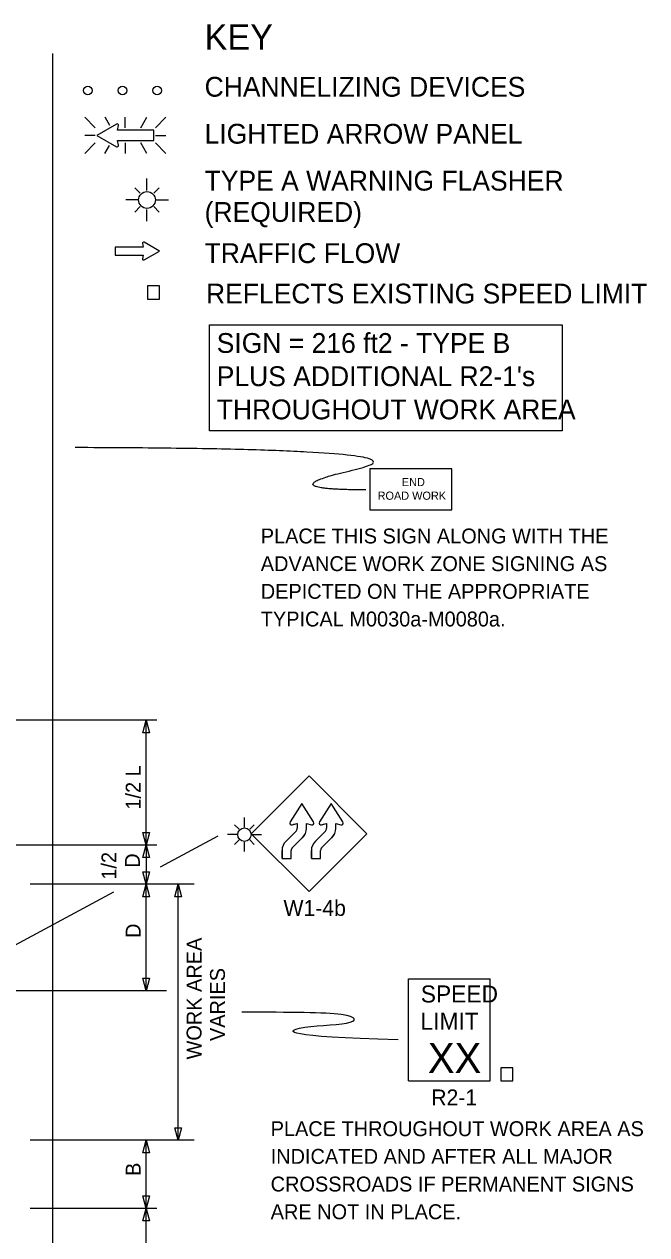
# Model space of a CAD drawing. Extents: x 16752 to 18475, y 7011 to 8262.
# Drawn here: x 17130 to 17423, y 7638 to 8206 of the extents above; entities that cross this region are included whole.
import ezdxf

# ---------------------------------------------------------------- set-up
doc = ezdxf.new("R2010")
doc.units = 0
for name, color, linetype in [('Level 3', 7, 'Continuous'), ('MT_SCRATCH_LEVEL_E', 7, 'Continuous'), ('PAVT_EDGE_EX', 7, 'Continuous'), ('TRAFFIC_SIGNS_PR', 7, 'Continuous'), ('TYPICAL_TEXT_DIMEN_EX', 7, 'Continuous'), ('TYPICAL_TEXT_DIMEN_PR', 7, 'Continuous')]:
    doc.layers.add(name, color=color, linetype=linetype)

msp = doc.modelspace()

# ---------------------------------------------------------------- linework, layer by layer
at = {"layer": 'Level 3'}
for p, q in [((17194.46, 7810.55), (17221.56, 7825.11)), ((17093.54, 7756.34), (17172.61, 7798.81))]:
    msp.add_line(p, q, dxfattribs=at)
at = {"layer": 'MT_SCRATCH_LEVEL_E'}
for p, q in [((17186.05, 8103.41), (17186.37, 8101.63)), ((17186.05, 8103.41), (17186.37, 8101.63)), ((17193.98, 8099.78), (17186.74, 8103.89)), ((17193.98, 8099.78), (17186.74, 8103.89)), ((17186.37, 8101.63), (17173.11, 8101.63)), ((17173.11, 8101.63), (17173.11, 8097.89)), ((17186.37, 8101.63), (17173.11, 8101.63)), ((17173.11, 8101.63), (17173.11, 8097.89)), ((17173.11, 8097.89), (17186.37, 8097.89)), ((17173.11, 8097.89), (17186.37, 8097.89)), ((17186.37, 8097.89), (17186.05, 8096.11)), ((17186.37, 8097.89), (17186.05, 8096.11)), ((17186.74, 8095.64), (17193.98, 8099.78)), ((17186.74, 8095.64), (17193.98, 8099.78))]:
    msp.add_line(p, q, dxfattribs=at)
for centre, start, end in [((17186.51, 8103.49), 60.4248, 189.9638), ((17186.51, 8103.49), 60.4248, 189.9638), ((17186.51, 8096.05), 170.0362, 299.7731), ((17186.51, 8096.05), 170.0362, 299.7731)]:
    msp.add_arc(centre, 0.463, start, end, dxfattribs=at)
at = {"layer": 'PAVT_EDGE_EX'}
msp.add_line((17143.71, 8192.65), (17143.71, 7386.98), dxfattribs=at)
at = {"layer": 'TRAFFIC_SIGNS_PR'}
for p, q in [((17158.86, 8162.62), (17163.8, 8157.69)), ((17170.63, 8158.8), (17168.42, 8162.62)), ((17177.95, 8157.69), (17177.95, 8162.62)), ((17185.18, 8157.69), (17188.03, 8162.62)), ((17192.1, 8157.69), (17197.03, 8162.62)), ((17163.8, 8154.13), (17158.86, 8154.13)), ((17192.1, 8154.13), (17197.03, 8154.13)), ((17158.86, 8145.64), (17163.8, 8150.57)), ((17168.38, 8145.64), (17170.49, 8149.3)), ((17177.95, 8150.57), (17177.95, 8145.64)), ((17188.08, 8145.64), (17185.23, 8150.57)), ((17192.1, 8150.57), (17197.03, 8145.64)), ((17188.13, 8128.22), (17188.13, 8133.84)), ((17184.99, 8126.92), (17182.36, 8129.55)), ((17191.27, 8126.92), (17193.9, 8129.55)), ((17184.19, 8123.78), (17178.15, 8123.78)), ((17184.99, 8120.64), (17182.36, 8118.01)), ((17191.27, 8120.64), (17193.9, 8118.01)), ((17192.07, 8123.78), (17198.16, 8123.78)), ((17188.13, 8113.83), (17188.13, 8119.34)), ((17264.29, 7853.25), (17237.14, 7826.1)), ((17291.45, 7826.1), (17264.29, 7853.25)), ((17231.4, 7828.19), (17229.29, 7830.3)), ((17233.91, 7829.23), (17233.91, 7833.73)), ((17236.43, 7828.19), (17238.53, 7830.3)), ((17230.76, 7825.67), (17225.92, 7825.67)), ((17237.07, 7825.67), (17241.95, 7825.67)), ((17237.14, 7826.1), (17264.29, 7798.94)), ((17253.43, 7822.63), (17258.14, 7827.35)), ((17258.14, 7827.34), (17253.43, 7822.63)), ((17256.48, 7819.58), (17261.19, 7824.29)), ((17256.48, 7819.58), (17261.19, 7824.29)), ((17264.29, 7798.94), (17291.45, 7826.1)), ((17267.22, 7822.63), (17271.94, 7827.35)), ((17271.94, 7827.34), (17267.22, 7822.63)), ((17270.27, 7819.58), (17274.99, 7824.29)), ((17270.28, 7819.58), (17274.99, 7824.29)), ((17231.4, 7823.16), (17229.29, 7821.05)), ((17233.91, 7817.71), (17233.91, 7822.12)), ((17236.43, 7823.16), (17238.53, 7821.05)), ((17251.56, 7814.51), (17251.56, 7818.21)), ((17251.56, 7814.51), (17255.88, 7814.51)), ((17255.88, 7814.51), (17255.88, 7818.21)), ((17265.36, 7814.51), (17265.36, 7818.21)), ((17265.36, 7814.51), (17269.67, 7814.51)), ((17269.67, 7814.51), (17269.67, 7818.21)), ((17310.96, 7757.98), (17349.36, 7757.98)), ((17310.96, 7709.98), (17310.96, 7757.98)), ((17349.36, 7709.98), (17349.36, 7757.98)), ((17310.96, 7709.98), (17349.36, 7709.98))]:
    msp.add_line(p, q, dxfattribs=at)
for points in [[(17173.87, 8159.41), (17164.58, 8154.13), (17173.88, 8148.81)], [(17174.75, 8149.44), (17174.35, 8151.7), (17191.36, 8151.7), (17191.36, 8156.51), (17174.35, 8156.51), (17174.75, 8158.79)], [(17266.35, 7831.62), (17260.86, 7840.23), (17255.38, 7831.62)], [(17266.35, 7831.62), (17260.86, 7840.23), (17255.38, 7831.62)], [(17280.14, 7831.62), (17274.66, 7840.23), (17269.18, 7831.62)], [(17280.14, 7831.62), (17274.66, 7840.23), (17269.18, 7831.62)], [(17256.34, 7830.32), (17258.7, 7830.97), (17258.7, 7828.68)], [(17256.34, 7830.32), (17257.18, 7830.55), (17258.7, 7830.97), (17258.7, 7828.68)], [(17263.02, 7828.6), (17263.02, 7830.97), (17265.38, 7830.32)], [(17263.02, 7828.6), (17263.02, 7830.97), (17265.38, 7830.32)], [(17270.14, 7830.32), (17272.5, 7830.97), (17272.5, 7828.68)], [(17270.14, 7830.32), (17270.97, 7830.55), (17272.5, 7830.97), (17272.5, 7828.68)], [(17276.81, 7828.6), (17276.82, 7830.97), (17279.18, 7830.32)], [(17276.81, 7828.6), (17276.82, 7830.97), (17279.18, 7830.32)], [(17251.56, 7818.21), (17251.56, 7814.51), (17255.88, 7814.51), (17255.88, 7818.21)], [(17265.36, 7818.21), (17265.36, 7814.51), (17269.67, 7814.51), (17269.67, 7818.21)]]:
    msp.add_lwpolyline(points, dxfattribs=at)
for points in [[(17188.41, 8077.24), (17194, 8077.24), (17194, 8083.41), (17188.41, 8083.41)], [(17292.84, 7978.23), (17331.24, 7978.23), (17331.24, 7997.43), (17292.84, 7997.43)], [(17354.38, 7709.98), (17359.97, 7709.98), (17359.97, 7716.15), (17354.38, 7716.15)]]:
    msp.add_lwpolyline(points, close=True, dxfattribs=at)
for centre, radius in [((17160.35, 8175.22), 2), ((17176.65, 8175.22), 2), ((17192.95, 8175.22), 2), ((17188.13, 8123.78), 3.94), ((17233.91, 7825.68), 3.15)]:
    msp.add_circle(centre, radius, dxfattribs=at)
for centre, radius, start, end in [((17174.16, 8158.88), 0.598, 350.7308, 118.8916), ((17174.16, 8149.33), 0.597, 241.4833, 9.9593), ((17256.11, 7831.16), 0.864, 147.5204, 285.3986), ((17256.11, 7831.16), 0.866, 147.5288, 285.3852), ((17265.61, 7831.16), 0.866, 254.6828, 32.2708), ((17265.61, 7831.16), 0.866, 254.6799, 32.2804), ((17262.53, 7819.9), 10.8, 74.68, 74.6808), ((17275.46, 7837.42), 10.8, 212.4569, 212.4665), ((17269.91, 7831.16), 0.864, 147.5204, 285.3986), ((17269.91, 7831.16), 0.866, 147.5288, 285.3852), ((17279.41, 7831.16), 0.866, 254.6828, 32.2708), ((17279.41, 7831.16), 0.866, 254.6799, 32.2804), ((17276.33, 7819.9), 10.8, 74.68, 74.6808), ((17289.25, 7837.42), 10.8, 212.4569, 212.4665), ((17256.85, 7828.67), 1.85, 314.2123, 0.1238), ((17256.85, 7828.67), 1.85, 314.2125, 0), ((17256.85, 7828.67), 6.17, 314.2125, 359.3819), ((17256.85, 7828.67), 6.17, 314.7687, 359.3755), ((17270.65, 7828.67), 1.85, 314.2123, 0.1238), ((17270.65, 7828.67), 1.85, 314.2125, 0), ((17270.65, 7828.67), 6.17, 314.2125, 359.3819), ((17270.65, 7828.67), 6.17, 314.7687, 359.3755), ((17257.73, 7818.21), 6.17, 134.2125, 180), ((17257.73, 7818.21), 6.17, 134.2125, 180), ((17257.73, 7818.21), 6.17, 134.2117, 180), ((17257.73, 7818.21), 1.85, 132.372, 180), ((17257.73, 7818.21), 1.85, 134.2125, 180), ((17271.52, 7818.21), 6.17, 134.2125, 180), ((17271.52, 7818.21), 6.17, 134.2125, 180), ((17271.52, 7818.21), 6.17, 134.2117, 180), ((17271.52, 7818.21), 1.85, 132.372, 180), ((17271.52, 7818.21), 1.85, 134.2125, 180)]:
    msp.add_arc(centre, radius, start, end, dxfattribs=at)
msp.add_open_spline([(17290.94, 7987.61), (17243.71, 7987.61), (17328.73, 8006.96), (17154.47, 8007.48)], degree=2, dxfattribs=at)
at = {"layer": 'TYPICAL_TEXT_DIMEN_EX'}
msp.add_lwpolyline([(17217.54, 8065.07), (17383.21, 8065.07), (17383.21, 8015.28), (17217.54, 8015.28)], close=True, dxfattribs=at)
at = {"layer": 'TYPICAL_TEXT_DIMEN_PR'}
for p, q in [((17192.71, 7879.39), (17084.13, 7879.39)), ((17186.14, 7873.53), (17187.71, 7879.39)), ((17187.71, 7820.75), (17187.71, 7879.39)), ((17187.71, 7879.39), (17189.28, 7873.53)), ((17187.71, 7873.53), (17186.14, 7873.53)), ((17189.28, 7873.53), (17187.71, 7873.53)), ((17187.71, 7820.75), (17186.14, 7826.61)), ((17186.14, 7826.61), (17187.71, 7826.61)), ((17187.71, 7826.61), (17189.28, 7826.61)), ((17189.28, 7826.61), (17187.71, 7820.75)), ((17192.71, 7820.75), (17042.88, 7820.75)), ((17186.14, 7814.89), (17187.71, 7820.75)), ((17187.71, 7820.75), (17189.28, 7814.89)), ((17187.71, 7820.75), (17187.71, 7802.34)), ((17187.71, 7814.89), (17186.14, 7814.89)), ((17189.28, 7814.89), (17187.71, 7814.89)), ((17187.71, 7802.34), (17186.14, 7808.2)), ((17186.14, 7808.2), (17187.71, 7808.2)), ((17187.71, 7808.2), (17189.28, 7808.2)), ((17189.28, 7808.2), (17187.71, 7802.34)), ((17210.36, 7802.34), (17133.22, 7802.34)), ((17186.14, 7796.48), (17187.71, 7802.34)), ((17187.71, 7752.34), (17187.71, 7802.34)), ((17187.71, 7802.34), (17189.28, 7796.48)), ((17201.14, 7796.48), (17202.71, 7802.34)), ((17202.71, 7682.16), (17202.71, 7802.34)), ((17202.71, 7802.34), (17204.28, 7796.48)), ((17187.71, 7796.48), (17186.14, 7796.48)), ((17189.28, 7796.48), (17187.71, 7796.48)), ((17202.71, 7796.48), (17201.14, 7796.48)), ((17204.28, 7796.48), (17202.71, 7796.48)), ((17187.71, 7752.34), (17186.14, 7758.2)), ((17186.14, 7758.2), (17187.71, 7758.2)), ((17187.71, 7758.2), (17189.28, 7758.2)), ((17189.28, 7758.2), (17187.71, 7752.34)), ((17197.31, 7752.34), (17109.47, 7752.34)), ((17202.71, 7682.16), (17201.14, 7688.03)), ((17201.14, 7688.03), (17202.71, 7688.03)), ((17202.71, 7688.03), (17204.28, 7688.03)), ((17204.28, 7688.03), (17202.71, 7682.16)), ((17210.36, 7682.16), (17133.22, 7682.16)), ((17186.14, 7676.3), (17187.71, 7682.16)), ((17187.71, 7650.11), (17187.71, 7682.16)), ((17187.71, 7682.16), (17189.28, 7676.3)), ((17187.71, 7676.3), (17186.14, 7676.3)), ((17189.28, 7676.3), (17187.71, 7676.3)), ((17187.71, 7650.11), (17186.14, 7655.97)), ((17186.14, 7655.97), (17187.71, 7655.97)), ((17187.71, 7650.11), (17186.14, 7655.97)), ((17186.14, 7655.97), (17187.71, 7655.97)), ((17187.71, 7655.97), (17189.28, 7655.97)), ((17189.28, 7655.97), (17187.71, 7650.11)), ((17187.71, 7655.97), (17189.28, 7655.97)), ((17189.28, 7655.97), (17187.71, 7650.11)), ((17192.71, 7650.11), (17133.22, 7650.11)), ((17192.71, 7650.11), (17133.22, 7650.11)), ((17186.14, 7644.24), (17187.71, 7650.11)), ((17186.14, 7644.24), (17187.71, 7650.11)), ((17187.71, 7650.11), (17189.28, 7644.24)), ((17187.71, 7586.44), (17187.71, 7650.11)), ((17187.71, 7650.11), (17189.28, 7644.24)), ((17187.71, 7586.44), (17187.71, 7650.11)), ((17187.71, 7644.24), (17186.14, 7644.24)), ((17187.71, 7644.24), (17186.14, 7644.24)), ((17189.28, 7644.24), (17187.71, 7644.24)), ((17189.28, 7644.24), (17187.71, 7644.24))]:
    msp.add_line(p, q, dxfattribs=at)
msp.add_open_spline([(17306.1, 7729.37), (17251.89, 7730.69), (17255.29, 7736.1), (17287.14, 7736.1), (17287.14, 7742.11), (17256.08, 7742.25), (17232.62, 7742.25)], degree=3, dxfattribs=at)

# ---------------------------------------------------------------- texts
at = {"layer": 'TRAFFIC_SIGNS_PR'}
for s, height, p in [('END', 3.831, (17307.84, 7989.36)), ('ROAD WORK', 3.831, (17296.45, 7982.97)), ('PLACE THIS SIGN ALONG WITH THE', 7, (17241.56, 7962.45)), ('ADVANCE WORK ZONE SIGNING AS', 7, (17241.56, 7949.45)), ('DEPICTED ON THE APPROPRIATE', 7, (17241.56, 7936.45)), ('TYPICAL M0030a-M0080a.', 7, (17241.56, 7923.45)), ('W1-4b', 7.44, (17252.25, 7787.51)), ('SPEED', 8, (17316.73, 7746.84)), ('LIMIT', 8, (17316.57, 7734.04)), ('XX', 14.031, (17320.08, 7713.74)), ('R2-1', 7.44, (17321.64, 7698.54)), ('PLACE THROUGHOUT WORK AREA AS', 7, (17246.22, 7684.06)), ('INDICATED AND AFTER ALL MAJOR', 7, (17246.22, 7671.06)), ('CROSSROADS IF PERMANENT SIGNS', 7, (17246.22, 7658.06)), ('ARE NOT IN PLACE.', 7, (17246.22, 7645.06))]:
    msp.add_text(s, height=height, dxfattribs=at).set_placement(p)
at = {"layer": 'TYPICAL_TEXT_DIMEN_EX'}
for s, height, p in [('KEY', 12, (17215.19, 8194.33)), ('CHANNELIZING DEVICES', 9.3, (17215.19, 8172.28)), ('LIGHTED ARROW PANEL', 9.3, (17215.19, 8150.23)), ('TYPE A WARNING FLASHER', 9.3, (17215.19, 8128.18)), ('(REQUIRED)', 9.3, (17215.19, 8113.48)), ('TRAFFIC FLOW', 9.3, (17215.19, 8094.15)), ('REFLECTS EXISTING SPEED LIMIT', 9.3, (17215.86, 8075.16)), ('SIGN = 216 ft2 - TYPE B', 9.3, (17220.88, 8051.95)), ("PLUS ADDITIONAL R2-1's", 9.3, (17220.88, 8036.35)), ('THROUGHOUT WORK AREA', 9.3, (17220.88, 8020.75))]:
    msp.add_text(s, height=height, dxfattribs=at).set_placement(p)
at = {"layer": 'TYPICAL_TEXT_DIMEN_PR'}
for s, p in [('1/2 L', (17185.15, 7837.43)), ('1/2', (17173.78, 7804.54)), ('D', (17184.78, 7810.11)), ('D', (17185.15, 7777.15)), ('WORK AREA', (17213.74, 7720.08)), ('VARIES', (17224.74, 7728.72)), ('B', (17185.15, 7665.37))]:
    msp.add_text(s, height=7, rotation=90, dxfattribs=at).set_placement(p)

doc.saveas('drawing.dxf')
